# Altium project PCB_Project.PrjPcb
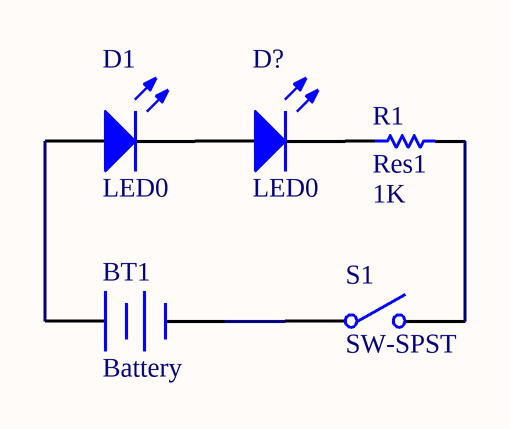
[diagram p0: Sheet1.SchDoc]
1 sheet, 5 parts. Net scope: global (net labels, ports and power ports of the same name join across sheets).
Board file: PCB1.PcbDoc

## Sheet Sheet1.SchDoc
size A4

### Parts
BT1  Battery  [BAT-2]
D1  LED0  [LED-0]
D?  LED0  [LED-0]
R1  Res1  value 1K  [AXIAL-0.3]
S1  SW-SPST  [SPST-2]

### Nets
NetBT1_1: BT1.1(+) D1.1(A)
NetBT1_2: BT1.2(-) S1.1(COMMON)
NetD1_2: D1.2(K) D?.1(A)
NetD?_2: D?.2(K) R1.1
NetR1_2: R1.2 S1.2(NO)

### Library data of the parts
BT1 = Battery: Multicell Battery
D1 D? = LED0: Typical INFRARED GaAs LED
R1 = Res1: Resistor
S1 = SW-SPST: Single-Pole, Single-Throw Switch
